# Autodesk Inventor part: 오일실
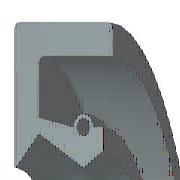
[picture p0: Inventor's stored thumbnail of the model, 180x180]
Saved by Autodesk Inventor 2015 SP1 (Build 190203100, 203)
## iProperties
Created: 2014-07
Part Number: 오일실
Material: 고무
Description: 오일-실
Document SubType Name: Modeling
Standard: KS B 2804
Designer: KYOUNG IL JANG
Standards Organization: KS
Language: ko-KR
Size Designation: D - 10 20 7
Categories: <MemberInstance><Categories><Category DisplayName="샤프트 부품" InternalName="7f7aeb1f-a693-4053-b835-cee3144e0d98" Mnemonic="SHFT"><Category DisplayName="실링" Intern
Density: 0.93 g/cm^3
Appearance: 고무 - 검은색 - 버전 1.1
Mass: 1.11329 g
Surface Area: 16.3871 cm^2
Volume: 1.19708 cm^3
Company: 한국ATC센터
IsCustomPart: 0
Author: KYOUNG IL JANG
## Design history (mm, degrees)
revolve "본체" stored, may be unused: angle "d17" = 90 deg
revolve "스프링1" stored, may be unused: angle "d18" = 90 deg
body "Solid1"
sketch "스케치1"
  geometry: L1 (0, 10)-(7, 10); L2 (7, 8.25)-(1.75, 8.25); L3 (1.75, 6.75)-(4.9, 5); L4 (4.9, 5)-(0, 5); L5 (0, 0)-(9.586, 0) reference; L6 (4.9, 5)-(6.3, 5.875); L7 (0, 18)-(0, -3) reference; L8 (-1.941, 0)-(11.507, 0) reference; L9 (4.2, 7.1)-(1.75, 7.59); L10 (1.75, 7.59)-(1.75, 8.25); L11 (0, 10)-(0, 5.088); L12 (4.9, 5)-(0, 5); L13 (1.75, 6.75)-(0.152, 5.028); L14 (7, 10)-(7, 8.25); L15 (5.6, 7.1)-(6.3, 7.1); L16 (6.3, 7.1)-(6.3, 5.875); C1 r 0.455 at (4.9, 7.1); A1 r 0.7 centre (4.9, 7.1) between (5.6, 7.1) and (4.2, 7.1); A2 r 0.088 centre (0.088, 5.088) between (0, 5.088) and (0.152, 5.028); 1 further point
  constraints: 28 end point, 5 horizontal alignment, 5 point on line, 4 point on circle, 4 vertical alignment, 3 centre point, 3 tangent, 2 collinear, 2 horizontal, 2 perpendicular, 1 coincident, 1 parallel
  dimensions: "d0" = 20 diameter of L1 L5 (= SD2); "d1" = 1.75 distance of L1.end L2.start (= SD); "d2" = 0.91 diameter of C1 (= SPDI); "d3" = 1.4 diameter of A1 (= SPDA); "d4" = 10 diameter of L3.end L5 (= NND); "d5" = 13.5 diameter of L3.start L5 (= TKDM); "d7" = 15.18 diameter of L9.end L5 (= TKDM + 0.24 x SWDT); "d8" = 1.75 distance between parallel lines of L11 L10 (= SD); "d9" = 4.9 distance from line of L11 C1.centre (= SPDST); "d10" = 14.2 diameter of C1.centre L5 (= HLDM); "d11" = 0.0875 radius of A2 (= 0.25 x LAB); "d12" = 6.3 distance between parallel lines of L11 L16 (= SDI); "d13" = 11.75 diameter of L6.end L5 (= ABDM); "d14" = 7 distance from line of L11 L1.end (= SWDT)
fillet "모깎기1" dims "d6" = 0.3 (= RR)
other parameters: "SD2" = 20 [user parameter; used in 1 equation term], "SWDT" = 7 [user parameter; used in 2 equation terms], "RR" = 0.3 [user parameter; used in 1 equation term], "SD" = 1.75 [user parameter; used in 2 equation terms], "NND" = 10 [user parameter; used in 1 equation term], "SPDA" = 1.4 [user parameter; used in 1 equation term], "SPDI" = 0.91 [user parameter; used in 1 equation term], "TKDM" = 13.5 [user parameter; used in 2 equation terms], "HLDM" = 14.2 [user parameter; used in 1 equation term], "ABDM" = 11.75 [user parameter; used in 1 equation term], "SDI" = 6.3 [user parameter; used in 1 equation term], "SPDST" = 4.9 [user parameter; used in 1 equation term], "LAB" = 0.35 [user parameter; used in 1 equation term], "d15" = 0, "d16" = 0, "d19" = 0
